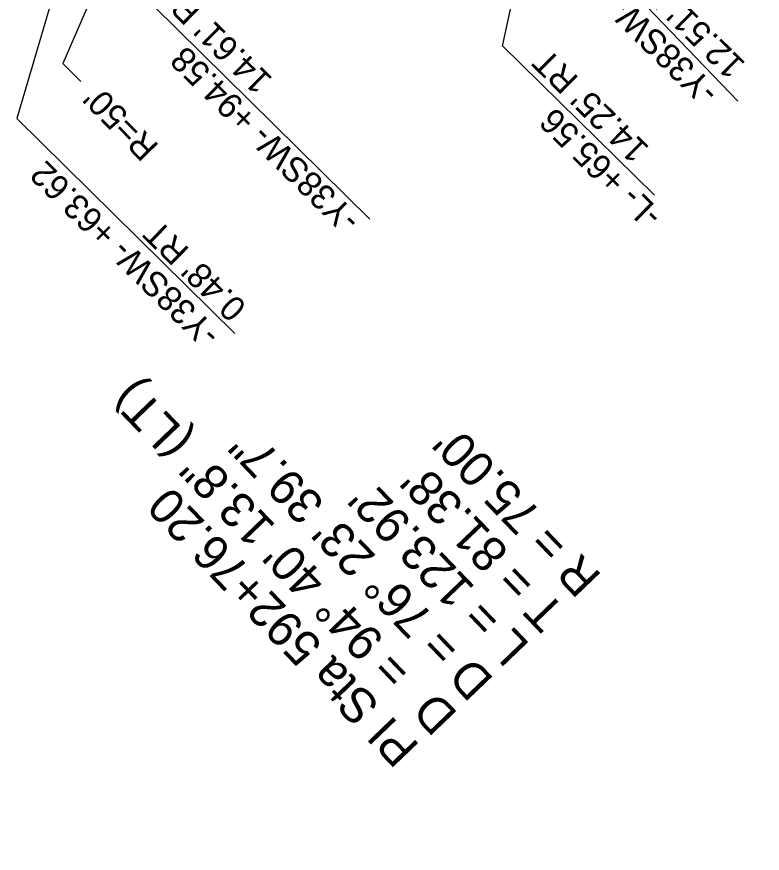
# Model space of a CAD drawing. Extents: x 1262642 to 1268358, y 767825 to 773481.
# Drawn here: x 1266688 to 1266837.7, y 771863.2 to 772031 of the extents above; entities that cross this region are included whole.
import ezdxf

# ---------------------------------------------------------------- set-up
doc = ezdxf.new("R2010")
doc.units = 0
for name, color, linetype in [('Prop Conc 1ft 6in Curb and Gutter', 7, 'Continuous'), ('Prop Dimension', 7, 'Continuous'), ('Prop Dimension Text', 7, 'Continuous'), ('Prop Horizontal Alignment', 7, 'Continuous'), ('Prop Horizontal Alignment Curve and Spiral Data', 7, 'Continuous'), ('Prop Lane Lines', 7, 'Continuous'), ('Prop Paved Shoulder', 7, 'Continuous'), ('Prop Shade Light', 7, 'Continuous')]:
    doc.layers.add(name, color=color, linetype=linetype)

msp = doc.modelspace()

# ---------------------------------------------------------------- linework, layer by layer
at = {"layer": 'Prop Conc 1ft 6in Curb and Gutter'}
msp.add_arc((1275047.31, 780021.23), 11414.25, 223.957867, 225.419319, dxfattribs=at)
at = {"layer": 'Prop Dimension'}
for p, q in [((1266722.9, 772128.88), (1266688.04, 772010.59)), ((1266728.03, 772092.2), (1266697.28, 772021.6))]:
    msp.add_line(p, q, dxfattribs=at)
at = {"layer": 'Prop Dimension Text'}
for p, q in [((1266832.76, 772014.09), (1266791.44, 772057.15)), ((1266715.46, 772033.19), (1266758.9, 771990.39)), ((1266785.57, 772025.2), (1266816.02, 771995.2)), ((1266697.28, 772021.6), (1266700.93, 772017.99)), ((1266731.82, 771967.47), (1266688.07, 772010.58))]:
    msp.add_line(p, q, dxfattribs=at)
msp.add_lwpolyline([(1266785.55, 772025.08), (1266789.08, 772041.54)], dxfattribs=at)
at = {"layer": 'Prop Horizontal Alignment'}
msp.add_arc((1275047.31, 780021.23), 11400, 222.993587, 225.404319, dxfattribs=at)
at = {"layer": 'Prop Lane Lines'}
msp.add_arc((1275047.31, 780021.23), 11427, 222.993587, 225.36373, dxfattribs=at)
at = {"layer": 'Prop Paved Shoulder'}
msp.add_arc((1275047.31, 780021.23), 11449, 223.936318, 225.443384, dxfattribs=at)
at = {"layer": 'Prop Shade Light'}
msp.add_arc((1275047.31, 780021.23), 11449, 223.936318, 225.443367, dxfattribs=at)

# ---------------------------------------------------------------- texts
at = {"layer": 'Prop Dimension'}
msp.add_text("R=50'", height=5, rotation=134.2575, dxfattribs=at).set_placement((1266716.78, 772005.12))
at = {"layer": 'Prop Dimension Text'}
for s, p in [('-Y38SW- +97.19', (1266829.25, 772016.27)), ("12.51' RT", (1266834.51, 772021.62)), ("14.61' RT", (1266739.6, 772018.57)), ('-Y38SW- +94.58', (1266757.3, 771990.6)), ("14.25' RT", (1266815.2, 772004.73)), ('-L- +65.56', (1266817.9, 771991.54)), ('-Y38SW- +63.62', (1266729.17, 771967.62)), ("0.48' RT", (1266734.44, 771972.96))]:
    msp.add_text(s, height=5, rotation=135.4239, dxfattribs=at).set_placement(p)
at = {"layer": 'Prop Horizontal Alignment Curve and Spiral Data'}
for s, p in [('= 94%%d 40\' 13.8" (LT)', (1266767.7, 771900.21)), ("R = 75.00'", (1266805.67, 771918.84)), ('D = 76%%d 23\' 39.7"', (1266784.02, 771898.07)), ("T = 81.38'", (1266798.45, 771911.91)), ('PI Sta 592+76.20', (1266769.12, 771884.71)), ("L = 123.92'", (1266791.24, 771904.99)), ('D', (1266776.8, 771891.14))]:
    msp.add_text(s, height=7, rotation=133.8119, dxfattribs=at).set_placement(p)

doc.saveas('drawing.dxf')
